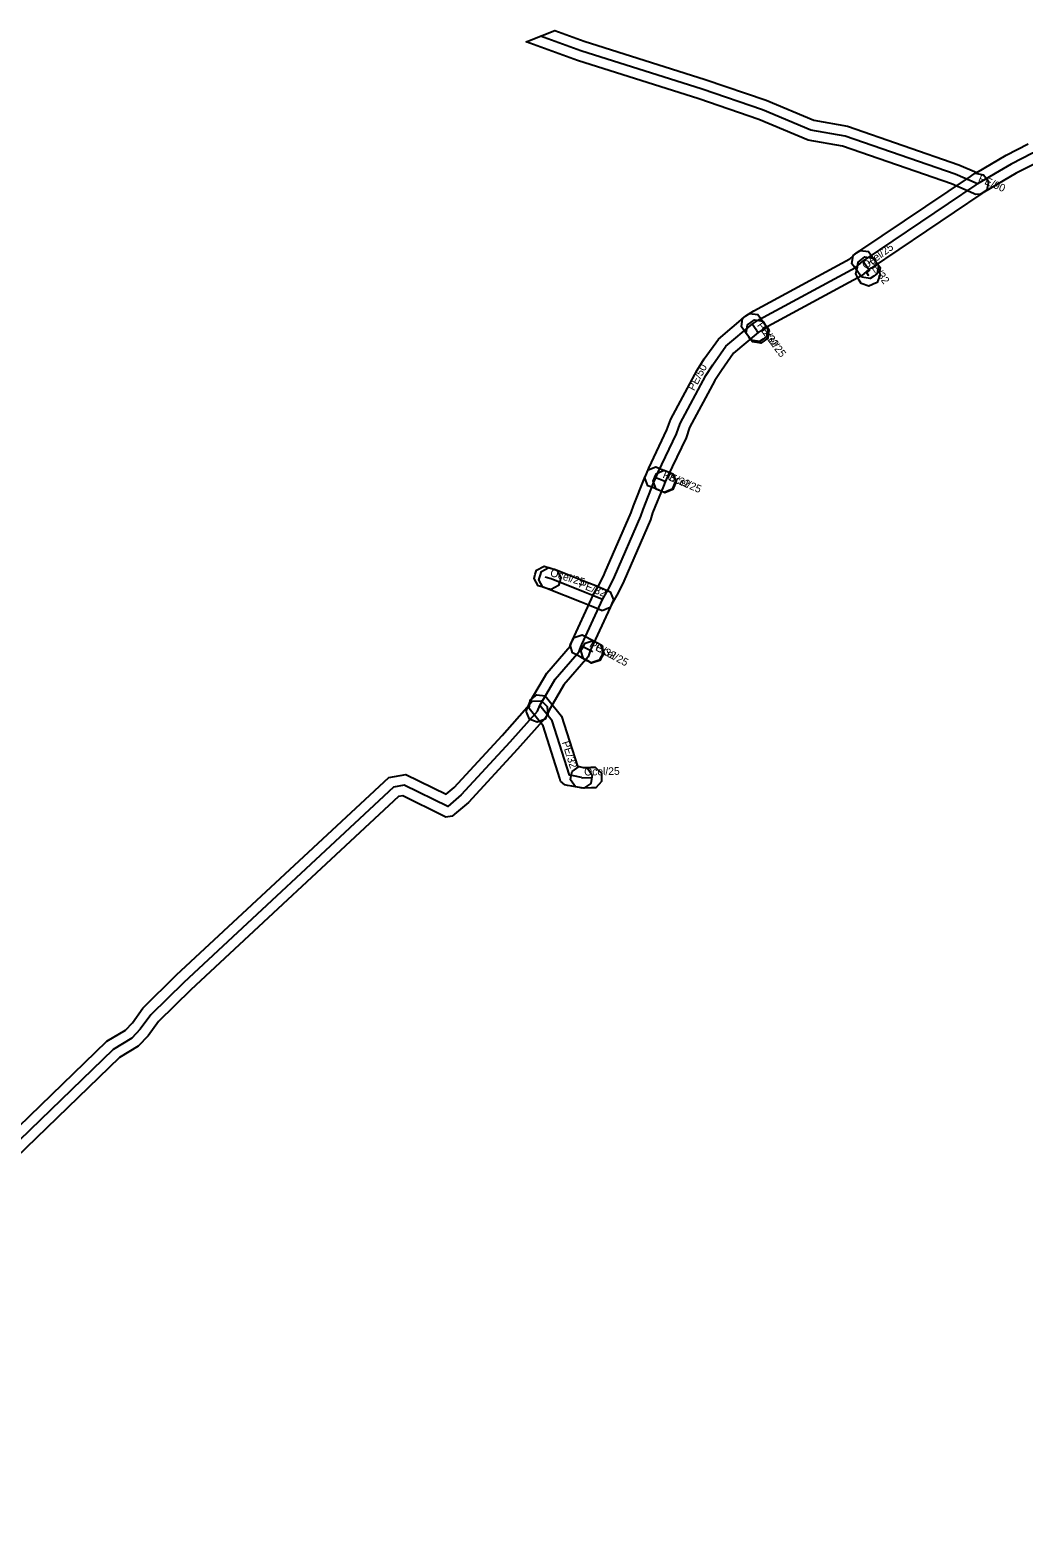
# Model space of a CAD drawing. Extents: x -677728 to -676939, y -1057290 to -1056960.
# Drawn here: x -677432.1 to -677335.3, y -1057237.5 to -1057090.6 of the extents above; entities that cross this region are included whole.
import ezdxf

# ---------------------------------------------------------------- set-up
doc = ezdxf.new("R2010")
doc.units = 0
for name, color, linetype in [('1', 7, 'Continuous'), ('24', 7, 'Continuous'), ('30', 7, 'Continuous')]:
    doc.layers.add(name, color=color, linetype=linetype)

msp = doc.modelspace()

# ---------------------------------------------------------------- linework, layer by layer
at = {"layer": '1'}
for points in [[(-677334.09, -1057103.48), (-677336.1, -1057104.49), (-677339.35, -1057106.41), (-677339.56, -1057106.53), (-677340.04, -1057106.56), (-677340.26, -1057106.47), (-677342.4, -1057105.53), (-677353.01, -1057101.87), (-677356.36, -1057101.27), (-677361.17, -1057099.26), (-677367, -1057097.26), (-677378.81, -1057093.52), (-677383.81, -1057091.71), (-677381.02, -1057090.59), (-677378.17, -1057091.62), (-677366.38, -1057095.36), (-677360.45, -1057097.39), (-677355.8, -1057099.33), (-677352.51, -1057099.93), (-677341.68, -1057103.67), (-677339.93, -1057104.43), (-677337.06, -1057102.73), (-677334.91, -1057101.64)], [(-677444.05, -1057207.86), (-677424.66, -1057189.08), (-677422.86, -1057188), (-677422.18, -1057187.28), (-677421.15, -1057185.85), (-677417.87, -1057182.63), (-677397.21, -1057163.39), (-677395.54, -1057163.09), (-677391.61, -1057165.02), (-677390.84, -1057164.37), (-677386.16, -1057159.28), (-677383.48, -1057156.27), (-677383.2, -1057155.96), (-677382.37, -1057155.91), (-677382.07, -1057156.18), (-677381.76, -1057156.46), (-677381.71, -1057157.29), (-677381.98, -1057157.59), (-677384.68, -1057160.62), (-677389.45, -1057165.81), (-677390.81, -1057166.97), (-677391.04, -1057167.17), (-677391.63, -1057167.24), (-677391.9, -1057167.11), (-677395.84, -1057165.17), (-677396.27, -1057165.25), (-677416.49, -1057184.07), (-677419.63, -1057187.15), (-677420.64, -1057188.56), (-677421.6, -1057189.58), (-677423.44, -1057190.68), (-677442.67, -1057209.3)]]:
    msp.add_lwpolyline(points, dxfattribs=at)
for points in [[(-677383.81, -1057156.92), (-677383.65, -1057156.54), (-677383.39, -1057155.92), (-677381.8, -1057153.21), (-677379.54, -1057150.58), (-677379.38, -1057150.17), (-677379.3, -1057149.99), (-677377.47, -1057145.98), (-677377.29, -1057145.58), (-677376.74, -1057144.66), (-677376.26, -1057143.7), (-677376.15, -1057143.44), (-677373.59, -1057137.56), (-677373.38, -1057136.91), (-677372.3, -1057134.23), (-677372.11, -1057133.79), (-677371.87, -1057133.23), (-677370.11, -1057129.52), (-677369.74, -1057128.48), (-677367.18, -1057123.69), (-677366.47, -1057122.6), (-677365.1, -1057120.67), (-677362.41, -1057118.41), (-677361.65, -1057117.91), (-677352.31, -1057112.85), (-677351.63, -1057112.26), (-677351.31, -1057112.06), (-677340.55, -1057104.81), (-677340.42, -1057104.72), (-677340.08, -1057104.49), (-677339.26, -1057104.65), (-677339.03, -1057104.99), (-677338.8, -1057105.33), (-677338.96, -1057106.15), (-677339.3, -1057106.38), (-677339.44, -1057106.47), (-677350.23, -1057113.76), (-677350.45, -1057113.88), (-677351.17, -1057114.51), (-677360.63, -1057119.63), (-677361.21, -1057120.01), (-677363.62, -1057122.03), (-677364.81, -1057123.72), (-677365.46, -1057124.71), (-677367.9, -1057129.28), (-677368.25, -1057130.28), (-677370.05, -1057134.05), (-677370.27, -1057134.57), (-677370.46, -1057135), (-677371.5, -1057137.6), (-677371.72, -1057138.28), (-677374.31, -1057144.24), (-677374.44, -1057144.54), (-677374.98, -1057145.62), (-677375.51, -1057146.52), (-677375.65, -1057146.81), (-677377.48, -1057150.83), (-677377.54, -1057150.95), (-677377.79, -1057151.62), (-677380.16, -1057154.37), (-677381.59, -1057156.82), (-677381.81, -1057157.32), (-677381.97, -1057157.71), (-677382.74, -1057158.01), (-677383.12, -1057157.85), (-677383.51, -1057157.69)], [(-677351.12, -1057114.64), (-677351.37, -1057114.31), (-677351.5, -1057114.12), (-677351.84, -1057113.67), (-677352.09, -1057113.33), (-677351.97, -1057112.51), (-677351.64, -1057112.27), (-677351.3, -1057112.02), (-677350.48, -1057112.14), (-677350.24, -1057112.47), (-677349.9, -1057112.94), (-677349.76, -1057113.12), (-677349.51, -1057113.45), (-677349.64, -1057114.27), (-677349.97, -1057114.52), (-677350.3, -1057114.76)], [(-677351.72, -1057114.31), (-677351.56, -1057113.61), (-677351.49, -1057113.16), (-677351.16, -1057112.91), (-677350.83, -1057112.66), (-677350.01, -1057112.78), (-677349.76, -1057113.12), (-677349.58, -1057113.36), (-677349.33, -1057113.7), (-677349.39, -1057114.11), (-677349.41, -1057114.23), (-677349.35, -1057114.36), (-677349.63, -1057115.14), (-677350.01, -1057115.31), (-677350.09, -1057115.35), (-677350.45, -1057115.51), (-677351.2, -1057115.26), (-677351.39, -1057114.92), (-677351.54, -1057114.64)], [(-677361.9, -1057120.78), (-677362.14, -1057120.45), (-677362.45, -1057120.03), (-677362.62, -1057119.8), (-677362.86, -1057119.47), (-677362.74, -1057118.65), (-677362.4, -1057118.4), (-677362.07, -1057118.16), (-677361.25, -1057118.28), (-677361, -1057118.62), (-677360.83, -1057118.85), (-677360.53, -1057119.26), (-677360.29, -1057119.6), (-677360.41, -1057120.42), (-677360.74, -1057120.66), (-677361.08, -1057120.91)], [(-677360.78, -1057118.93), (-677360.53, -1057119.26), (-677360.41, -1057119.42), (-677360.17, -1057119.76), (-677360.29, -1057120.57), (-677360.63, -1057120.82), (-677360.96, -1057121.06), (-677361.78, -1057120.94), (-677362.03, -1057120.6), (-677362.14, -1057120.45), (-677362.39, -1057120.11), (-677362.26, -1057119.29), (-677361.93, -1057119.05), (-677361.59, -1057118.8)], [(-677370.38, -1057135.6), (-677370.76, -1057135.44), (-677371.26, -1057135.23), (-677371.57, -1057135.1), (-677371.96, -1057134.95), (-677372.27, -1057134.18), (-677372.11, -1057133.8), (-677371.95, -1057133.41), (-677371.19, -1057133.1), (-677370.81, -1057133.26), (-677370.5, -1057133.39), (-677369.99, -1057133.59), (-677369.61, -1057133.75), (-677369.29, -1057134.52), (-677369.45, -1057134.9), (-677369.61, -1057135.28)], [(-677370.37, -1057133.44), (-677369.99, -1057133.6), (-677369.9, -1057133.63), (-677369.52, -1057133.79), (-677369.2, -1057134.56), (-677369.37, -1057134.94), (-677369.53, -1057135.32), (-677370.3, -1057135.64), (-677370.68, -1057135.48), (-677370.77, -1057135.44), (-677371.15, -1057135.28), (-677371.46, -1057134.51), (-677371.3, -1057134.13), (-677371.14, -1057133.75)], [(-677381.4, -1057145.08), (-677381.8, -1057144.97), (-677382.26, -1057144.82), (-677382.66, -1057144.71), (-677383.05, -1057143.98), (-677382.93, -1057143.58), (-677382.81, -1057143.18), (-677382.08, -1057142.79), (-677381.68, -1057142.91), (-677381.22, -1057143.05), (-677380.82, -1057143.17), (-677380.43, -1057143.9), (-677380.55, -1057144.3), (-677380.67, -1057144.69)], [(-677376.41, -1057147.13), (-677376.79, -1057146.97), (-677377.8, -1057146.55), (-677378.45, -1057146.29), (-677381.73, -1057144.99), (-677381.8, -1057144.97), (-677382.19, -1057144.84), (-677382.58, -1057144.11), (-677382.46, -1057143.72), (-677382.34, -1057143.32), (-677381.61, -1057142.93), (-677381.22, -1057143.05), (-677381.07, -1057143.09), (-677377.71, -1057144.43), (-677377.04, -1057144.69), (-677376.01, -1057145.13), (-677375.63, -1057145.29), (-677375.32, -1057146.06), (-677375.48, -1057146.44), (-677375.64, -1057146.82)], [(-677377.5, -1057152.2), (-677377.87, -1057152.01), (-677378.51, -1057151.67), (-677378.93, -1057151.44), (-677379.3, -1057151.25), (-677379.54, -1057150.46), (-677379.34, -1057150.09), (-677379.15, -1057149.73), (-677378.36, -1057149.48), (-677377.99, -1057149.68), (-677377.57, -1057149.9), (-677376.93, -1057150.24), (-677376.57, -1057150.43), (-677376.32, -1057151.22), (-677376.52, -1057151.59), (-677376.71, -1057151.96)], [(-677377.29, -1057150.04), (-677376.93, -1057150.24), (-677376.87, -1057150.27), (-677376.51, -1057150.47), (-677376.27, -1057151.26), (-677376.46, -1057151.62), (-677376.66, -1057151.99), (-677377.45, -1057152.23), (-677377.82, -1057152.03), (-677377.87, -1057152), (-677378.24, -1057151.81), (-677378.48, -1057151.01), (-677378.28, -1057150.65), (-677378.08, -1057150.28)], [(-677380.38, -1057157.4), (-677378.83, -1057162.29), (-677378.26, -1057162.4), (-677377.85, -1057162.47), (-677377.38, -1057163.16), (-677377.46, -1057163.56), (-677377.53, -1057163.97), (-677378.22, -1057164.44), (-677378.62, -1057164.37), (-677379.38, -1057164.23), (-677379.78, -1057164.15), (-677380.05, -1057164.1), (-677380.47, -1057163.74), (-677380.55, -1057163.47), (-677382.18, -1057158.36), (-677383.27, -1057157), (-677383.53, -1057156.67), (-677383.44, -1057155.85), (-677383.11, -1057155.59), (-677382.79, -1057155.33), (-677381.97, -1057155.42), (-677381.71, -1057155.75)], [(-677378.67, -1057162.32), (-677378.26, -1057162.4), (-677378.21, -1057162.41), (-677377.51, -1057162.39), (-677377.09, -1057162.38), (-677376.49, -1057162.95), (-677376.48, -1057163.37), (-677376.47, -1057163.78), (-677377.05, -1057164.38), (-677377.46, -1057164.39), (-677378.37, -1057164.41), (-677378.62, -1057164.37), (-677379.03, -1057164.29), (-677379.5, -1057163.61), (-677379.43, -1057163.2), (-677379.35, -1057162.79)]]:
    msp.add_lwpolyline(points, close=True, dxfattribs=at)
at = {"layer": '24'}
for points in [[(-677297.94, -1057090.56), (-677298.31, -1057090.56), (-677298.46, -1057090.56), (-677305.26, -1057093.21), (-677307.17, -1057093.59), (-677307.78, -1057093.77), (-677313.55, -1057095.69), (-677315.11, -1057096.18), (-677321.27, -1057098.08), (-677322.67, -1057098.53), (-677322.86, -1057098.59), (-677331.24, -1057101.31), (-677332.46, -1057101.78), (-677334.5, -1057102.56), (-677336.58, -1057103.61), (-677339.86, -1057105.55), (-677342.04, -1057104.6), (-677352.76, -1057100.9), (-677356.08, -1057100.3), (-677360.81, -1057098.32), (-677366.69, -1057096.31), (-677378.49, -1057092.57), (-677382.42, -1057091.15)], [(-677382.73, -1057156.93), (-677382.49, -1057156.37), (-677380.98, -1057153.79), (-677378.66, -1057151.1), (-677378.46, -1057150.56), (-677378.39, -1057150.41), (-677376.56, -1057146.4), (-677376.4, -1057146.05), (-677375.86, -1057145.14), (-677375.35, -1057144.12), (-677375.23, -1057143.84), (-677372.66, -1057137.92), (-677372.44, -1057137.26), (-677371.38, -1057134.62), (-677371.19, -1057134.18), (-677370.96, -1057133.64), (-677369.18, -1057129.9), (-677368.82, -1057128.88), (-677366.32, -1057124.2), (-677365.64, -1057123.16), (-677364.36, -1057121.35), (-677361.81, -1057119.21), (-677361.14, -1057118.77), (-677351.74, -1057113.68), (-677351.04, -1057113.07), (-677350.77, -1057112.91), (-677339.99, -1057105.64), (-677339.86, -1057105.55)], [(-677350.56, -1057113.71), (-677350.7, -1057113.53), (-677351.04, -1057113.07)], [(-677350.56, -1057113.71), (-677350.38, -1057113.96), (-677350.66, -1057114.16), (-677350.51, -1057114.44), (-677350.43, -1057114.4)], [(-677361.34, -1057119.85), (-677361.64, -1057119.44), (-677361.81, -1057119.21)], [(-677361.34, -1057119.85), (-677361.22, -1057120.01)], [(-677370.38, -1057134.52), (-677370.88, -1057134.31), (-677371.19, -1057134.18)], [(-677370.38, -1057134.52), (-677370.29, -1057134.55)], [(-677381.51, -1057144.01), (-677381.97, -1057143.87)], [(-677376.4, -1057146.05), (-677377.42, -1057145.62), (-677378.08, -1057145.36), (-677381.4, -1057144.04), (-677381.51, -1057144.01)], [(-677377.4, -1057151.12), (-677378.04, -1057150.78), (-677378.46, -1057150.56)], [(-677377.4, -1057151.12), (-677377.35, -1057151.15)], [(-677382.73, -1057156.93), (-677385.42, -1057159.95), (-677390.15, -1057165.09), (-677391.46, -1057166.21), (-677395.69, -1057164.13), (-677396.74, -1057164.32), (-677417.18, -1057183.35), (-677420.39, -1057186.5), (-677421.41, -1057187.92), (-677422.23, -1057188.79), (-677424.05, -1057189.88), (-677443.36, -1057208.58), (-677453.77, -1057218.42), (-677461.52, -1057225.25), (-677463.37, -1057226.45), (-677465.97, -1057227.04), (-677481.66, -1057227.09), (-677497.47, -1057226.96), (-677504.2, -1057227.37), (-677512.73, -1057228.88), (-677524.31, -1057232.82), (-677534.84, -1057237.48)], [(-677378.44, -1057163.38), (-677379.2, -1057163.24), (-677379.6, -1057163.17), (-677381.28, -1057157.88), (-677382.49, -1057156.37)], [(-677378.44, -1057163.38), (-677378.29, -1057163.41), (-677377.48, -1057163.39)]]:
    msp.add_lwpolyline(points, dxfattribs=at)

# ---------------------------------------------------------------- texts
at = {"layer": '30'}
for s, rotation, p in [('PE/90', 336.4534, (-677339.85, -1057105.27)), ('Ocel/25', 36.1736, (-677350.76, -1057113.89)), ('PE/32', 306.5497, (-677350.6, -1057113.19)), ('PE/32', 306.3136, (-677361.37, -1057119.33)), ('Ocel/25', 306.2853, (-677361.08, -1057119.73)), ('PE/50', 61.8894, (-677367.46, -1057125.76)), ('PE/32', 337.4937, (-677370.58, -1057134.15)), ('Ocel/25', 337.1094, (-677370.13, -1057134.34)), ('Ocel/25', 343.176, (-677381.54, -1057143.74)), ('PE/32', 338.3506, (-677378.75, -1057144.81)), ('PE/32', 332.0945, (-677377.73, -1057150.64)), ('Ocel/25', 331.7626, (-677377.17, -1057150.94)), ('PE/32', 287.6188, (-677380.35, -1057159.96)), ('Ocel/25', 1.3487, (-677378.16, -1057163.2))]:
    msp.add_text(s, height=0.75, rotation=rotation, dxfattribs=at).set_placement(p)

doc.saveas('drawing.dxf')
